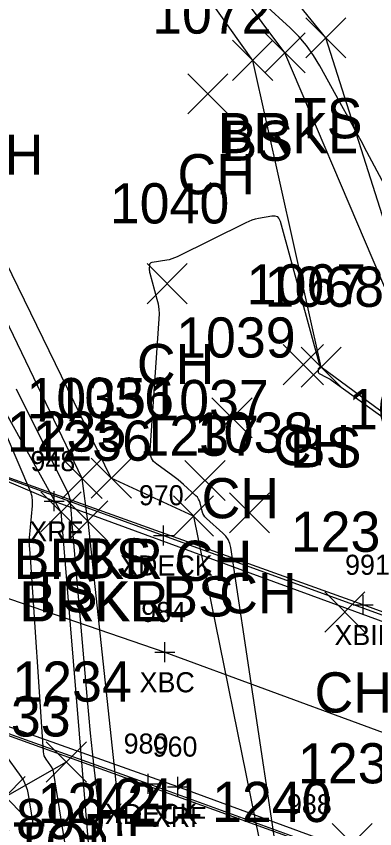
# Model space of a CAD drawing. Extents: x 1592612 to 1596497, y 111838 to 113741.
# Drawn here: x 1592864.37 to 1592882.21, y 113442.94 to 113483.39 of the extents above; entities that cross this region are included whole.
import ezdxf

# ---------------------------------------------------------------- set-up
doc = ezdxf.new("R2010")
doc.units = 0
for name, color, linetype in [('B_A', 7, 'Continuous'), ('B_I', 7, 'Continuous'), ('B_TIC', 7, 'Continuous'), ('BB', 7, 'Continuous'), ('BELB', 7, 'Continuous'), ('BR', 7, 'Continuous'), ('L_A', 7, 'Continuous'), ('L_I', 7, 'Continuous'), ('L_TIC', 7, 'Continuous'), ('LASF', 7, 'Continuous'), ('LAWE', 7, 'Continuous'), ('LELB', 7, 'Continuous'), ('LSOGCMI', 7, 'Continuous')]:
    doc.layers.add(name, color=color, linetype=linetype)

msp = doc.modelspace()

# ---------------------------------------------------------------- linework, layer by layer
at = {"layer": 'B_TIC'}
for p, q in [((1592866.258, 113459.246), (1592866.334, 113459.246)), ((1592871.698, 113457.547), (1592871.773, 113457.547)), ((1592881.637, 113454.085), (1592881.713, 113454.085)), ((1592871.771, 113451.736), (1592871.847, 113451.736)), ((1592870.939, 113445.184), (1592871.015, 113445.184)), ((1592872.405, 113445.033), (1592872.481, 113445.033))]:
    msp.add_line(p, q, dxfattribs=at)
for points in [[(1592866.255, 113458.746), (1592866.255, 113459.746)], [(1592865.755, 113459.246), (1592866.755, 113459.246)], [(1592871.694, 113457.047), (1592871.694, 113458.047)], [(1592871.194, 113457.547), (1592872.194, 113457.547)], [(1592881.634, 113453.585), (1592881.634, 113454.585)], [(1592881.134, 113454.085), (1592882.134, 113454.085)], [(1592871.768, 113451.236), (1592871.768, 113452.236)], [(1592871.268, 113451.736), (1592872.268, 113451.736)], [(1592870.936, 113444.684), (1592870.936, 113445.684)], [(1592872.402, 113444.533), (1592872.402, 113445.533)], [(1592870.436, 113445.184), (1592871.436, 113445.184)], [(1592871.902, 113445.033), (1592872.902, 113445.033)]]:
    msp.add_lwpolyline(points, dxfattribs=at)
at = {"layer": 'BB'}
for points in [[(1592909.632, 113443.83), (1592881.634, 113454.085), (1592854.88, 113463.68)], [(1592851.635, 113452.04), (1592879.022, 113442.165), (1592905.868, 113432.599)]]:
    msp.add_lwpolyline(points, dxfattribs=at)
at = {"layer": 'BELB'}
for points in [[(1592854.955, 113463.655), (1592871.694, 113457.547), (1592891.845, 113450.228), (1592909.596, 113443.74)], [(1592853.101, 113458.134), (1592871.768, 113451.736), (1592891.615, 113444.426), (1592907.694, 113438.543)], [(1592905.752, 113432.884), (1592904.3, 113433.154), (1592890.285, 113438.142), (1592870.936, 113445.184), (1592851.173, 113452.262)]]:
    msp.add_lwpolyline(points, dxfattribs=at)
at = {"layer": 'BR'}
for points in [[(1592852.564, 113465.029), (1592855.944, 113463.638), (1592866.255, 113459.246), (1592887.597, 113451.431), (1592909.085, 113443.965), (1592911.825, 113443.005)], [(1592908.092, 113431.674), (1592904.666, 113433.279), (1592893.882, 113437.15), (1592872.402, 113445.033), (1592848.761, 113453.419)]]:
    msp.add_lwpolyline(points, dxfattribs=at)
at = {"layer": 'L_TIC'}
for points in [[(1592878.778, 113481.314), (1592880.778, 113483.314)], [(1592880.778, 113481.314), (1592878.778, 113483.314)], [(1592876.744, 113480.574), (1592878.744, 113482.574)], [(1592878.744, 113480.574), (1592876.744, 113482.574)], [(1592875.137, 113480.194), (1592877.137, 113482.194)], [(1592877.137, 113480.194), (1592875.137, 113482.194)], [(1592872.901, 113478.528), (1592874.901, 113480.528)], [(1592874.901, 113478.528), (1592872.901, 113480.528)], [(1592870.88, 113469.078), (1592872.88, 113471.078)], [(1592872.88, 113469.078), (1592870.88, 113471.078)], [(1592877.654, 113465.043), (1592879.654, 113467.043)], [(1592879.654, 113465.043), (1592877.654, 113467.043)], [(1592878.544, 113464.926), (1592880.544, 113466.926)], [(1592880.544, 113464.926), (1592878.544, 113466.926)], [(1592874.103, 113462.399), (1592876.103, 113464.399)], [(1592876.103, 113462.399), (1592874.103, 113464.399)], [(1592866.645, 113459.38), (1592868.645, 113461.38)], [(1592868.645, 113459.38), (1592866.645, 113461.38)], [(1592868.098, 113459.398), (1592870.098, 113461.398)], [(1592870.098, 113459.398), (1592868.098, 113461.398)], [(1592872.762, 113459.283), (1592874.762, 113461.283)], [(1592874.762, 113459.283), (1592872.762, 113461.283)], [(1592865.59, 113457.717), (1592867.59, 113459.717)], [(1592867.59, 113457.717), (1592865.59, 113459.717)], [(1592874.976, 113457.667), (1592876.976, 113459.667)], [(1592876.976, 113457.667), (1592874.976, 113459.667)], [(1592866.922, 113457.263), (1592868.922, 113459.263)], [(1592868.922, 113457.263), (1592866.922, 113459.263)], [(1592866.922, 113457.263), (1592868.922, 113459.263)], [(1592868.922, 113457.263), (1592866.922, 113459.263)], [(1592872.192, 113457.509), (1592874.192, 113459.509)], [(1592874.192, 113457.509), (1592872.192, 113459.509)], [(1592879.724, 113452.73), (1592881.724, 113454.73)], [(1592881.724, 113452.73), (1592879.724, 113454.73)], [(1592865.863, 113445.27), (1592867.863, 113447.27)], [(1592867.863, 113445.27), (1592865.863, 113447.27)], [(1592865.863, 113445.27), (1592867.863, 113447.27)], [(1592867.863, 113445.27), (1592865.863, 113447.27)], [(1592862.817, 113443.537), (1592864.817, 113445.537)], [(1592864.817, 113443.537), (1592862.817, 113445.537)], [(1592862.817, 113443.537), (1592864.817, 113445.537)], [(1592864.817, 113443.537), (1592862.817, 113445.537)], [(1592880.09, 113441.203), (1592882.09, 113443.203)], [(1592882.09, 113441.203), (1592880.09, 113443.203)]]:
    msp.add_lwpolyline(points, dxfattribs=at)
at = {"layer": 'LASF'}
msp.add_lwpolyline([(1592859.003, 113448.358), (1592863.817, 113444.537), (1592866.863, 113446.27)], dxfattribs=at)
at = {"layer": 'LAWE'}
for points in [[(1592886.537, 113460.922), (1592877.744, 113481.574), (1592863.095, 113501.144), (1592852.902, 113518.209), (1592848.805, 113541.382), (1592835.879, 113571.623), (1592826.212, 113589.998), (1592821.08, 113603.103), (1592811.502, 113625.047), (1592801.909, 113656.496), (1592787.746, 113677.481), (1592769.551, 113701.793), (1592752.509, 113717.946)], [(1592867.645, 113460.38), (1592859.409, 113477.515), (1592844.793, 113495.549), (1592832.37, 113516.6), (1592826.928, 113530.545), (1592818.762, 113547.936), (1592807.597, 113581.108), (1592797.669, 113603.177), (1592787.513, 113626.88), (1592776.477, 113646.362), (1592766.38, 113665.342), (1592748.736, 113682.085), (1592730.356, 113695.945)], [(1592867.923, 113458.263), (1592867.645, 113460.38)], [(1592867.923, 113458.263), (1592869.843, 113440.453), (1592871.967, 113422.356), (1592872.93, 113405.001), (1592883.346, 113373.9), (1592893.179, 113344.656), (1592901.657, 113316.308), (1592912.684, 113311.087), (1592910.248, 113308.35), (1592916.07, 113291.076)]]:
    msp.add_lwpolyline(points, dxfattribs=at)
at = {"layer": 'LELB'}
for points in [[(1592886.583, 113460.952), (1592879.778, 113482.315), (1592863.966, 113501.755), (1592853.366, 113518.29), (1592851.192, 113542.037), (1592841.019, 113567.093), (1592831.516, 113591.894), (1592821.816, 113602.808), (1592813.329, 113624.79), (1592804.232, 113657.067), (1592789.644, 113678.369), (1592770.935, 113703.549), (1592752.623, 113718.428)], [(1592886.43, 113460.851), (1592879.543, 113465.926), (1592876.137, 113481.194), (1592862.304, 113500.643), (1592852.529, 113517.932), (1592848.162, 113540.894), (1592835.177, 113571.255), (1592825.196, 113589.927), (1592820.421, 113603.303), (1592810.027, 113625.391), (1592799.468, 113655.332), (1592786.607, 113676.744), (1592768.899, 113700.806), (1592752.213, 113717.027)], [(1592869.098, 113460.398), (1592860.441, 113478.115), (1592844.631, 113496.556), (1592834.165, 113516.964), (1592828.396, 113531.171), (1592823.559, 113549.918), (1592808.456, 113581.723), (1592799.527, 113603.061), (1592789.48, 113627.849), (1592777.21, 113647.427), (1592766.461, 113666.146), (1592749.422, 113683.288), (1592730.933, 113697.021)], [(1592866.59, 113458.717), (1592856.492, 113476.867)], [(1592873.192, 113458.509), (1592869.098, 113460.398)], [(1592866.59, 113458.717), (1592868.12, 113440.226), (1592870.678, 113422.668), (1592871.235, 113404.668), (1592883.079, 113373.124), (1592885.764, 113364.063), (1592892.434, 113344.134), (1592901.184, 113316.355)], [(1592873.192, 113458.509), (1592876.893, 113440.279), (1592874.766, 113422.722), (1592874.598, 113405.543), (1592883.851, 113374.09), (1592893.431, 113344.94), (1592902.258, 113316.43), (1592913.374, 113311.383), (1592911.324, 113309.219), (1592917.546, 113291.093), (1592922.314, 113282.948), (1592911.412, 113283.497), (1592902.691, 113283.749), (1592891.129, 113289.026)]]:
    msp.add_lwpolyline(points, dxfattribs=at)
at = {"layer": 'LSOGCMI'}
for points in [[(1592886.153, 113468.55), (1592881.816, 113476.647), (1592881.528, 113477.184), (1592881.238, 113477.72), (1592880.947, 113478.255), (1592880.654, 113478.789), (1592879.48, 113480.925), (1592879.167, 113481.443), (1592878.815, 113481.932), (1592878.425, 113482.389), (1592877.995, 113482.816), (1592875.379, 113485.215)], [(1592877.274, 113442.136), (1592875.051, 113456.937), (1592875.002, 113457.145), (1592874.92, 113457.336), (1592874.805, 113457.508), (1592874.657, 113457.663), (1592873.833, 113458.394), (1592873.76, 113458.469), (1592873.7, 113458.553), (1592873.654, 113458.645), (1592873.622, 113458.746), (1592873.52, 113459.164), (1592873.488, 113459.265), (1592873.443, 113459.357), (1592873.383, 113459.442), (1592873.311, 113459.518), (1592872.695, 113460.08), (1592872.564, 113460.196), (1592872.43, 113460.308), (1592872.293, 113460.416), (1592872.153, 113460.52), (1592871.359, 113461.09), (1592871.204, 113461.231), (1592871.098, 113461.394), (1592871.04, 113461.581), (1592871.031, 113461.79), (1592871.485, 113468.335), (1592871.491, 113468.577), (1592871.478, 113468.816), (1592871.444, 113469.053), (1592871.389, 113469.289), (1592871.032, 113470.589), (1592871.02, 113470.642), (1592871.011, 113470.695), (1592871.007, 113470.749), (1592871.007, 113470.803), (1592871.016, 113471.021), (1592871.024, 113471.07), (1592871.046, 113471.107), (1592871.08, 113471.133), (1592871.128, 113471.147), (1592871.862, 113471.262), (1592872.001, 113471.289), (1592872.136, 113471.327), (1592872.268, 113471.375), (1592872.397, 113471.433), (1592875.807, 113473.128), (1592875.958, 113473.196), (1592876.112, 113473.254), (1592876.27, 113473.3), (1592876.432, 113473.335), (1592877.086, 113473.452), (1592877.235, 113473.458), (1592877.354, 113473.416), (1592877.443, 113473.327), (1592877.501, 113473.19), (1592879.48, 113465.966), (1592879.483, 113465.95), (1592879.481, 113465.936), (1592879.475, 113465.922), (1592879.465, 113465.91), (1592879.417, 113465.864), (1592879.407, 113465.852), (1592879.399, 113465.838), (1592879.395, 113465.823), (1592879.394, 113465.807), (1592879.399, 113465.686), (1592879.402, 113465.662), (1592879.411, 113465.642), (1592879.426, 113465.625), (1592879.446, 113465.612), (1592879.799, 113465.432), (1592879.865, 113465.397), (1592879.929, 113465.36), (1592879.992, 113465.32), (1592880.053, 113465.278), (1592886.206, 113460.843)], [(1592864.359, 113464.844), (1592866.943, 113459.627), (1592866.987, 113459.526), (1592867.021, 113459.423), (1592867.044, 113459.316), (1592867.057, 113459.207), (1592867.089, 113458.763), (1592867.097, 113458.652), (1592867.105, 113458.541), (1592867.114, 113458.431), (1592867.124, 113458.32), (1592867.879, 113449.549), (1592867.962, 113448.625), (1592868.051, 113447.701), (1592868.148, 113446.779), (1592868.25, 113445.857), (1592868.675, 113442.17)], [(1592866.86, 113441.768), (1592866.244, 113445.696), (1592866.223, 113445.795), (1592866.19, 113445.891), (1592866.147, 113445.981), (1592866.093, 113446.067), (1592865.853, 113446.402), (1592865.799, 113446.489), (1592865.759, 113446.579), (1592865.733, 113446.675), (1592865.719, 113446.776), (1592865.071, 113456.467), (1592865.065, 113456.548), (1592865.06, 113456.628), (1592865.054, 113456.709), (1592865.047, 113456.789), (1592865.022, 113457.111), (1592865.017, 113457.191), (1592865.016, 113457.271), (1592865.019, 113457.352), (1592865.025, 113457.432), (1592865.179, 113459.023), (1592865.183, 113459.08), (1592865.184, 113459.137), (1592865.183, 113459.194), (1592865.178, 113459.251), (1592865.153, 113459.48), (1592865.145, 113459.536), (1592865.133, 113459.591), (1592865.116, 113459.646), (1592865.095, 113459.699), (1592863.13, 113464.241)], [(1592863.786, 113446.674), (1592864.589, 113445.551), (1592864.722, 113445.341), (1592864.828, 113445.121), (1592864.907, 113444.889), (1592864.959, 113444.647), (1592865.169, 113443.307), (1592865.175, 113443.234), (1592865.168, 113443.164), (1592865.149, 113443.095), (1592865.119, 113443.029), (1592864.972, 113442.769)]]:
    msp.add_lwpolyline(points, dxfattribs=at)

# ---------------------------------------------------------------- texts
at = {"layer": 'B_A'}
for s, p in [('XRF', (1592865.015, 113457.246)), ('XDECK', (1592869.537, 113455.547)), ('XBIB', (1592880.205, 113452.085)), ('XBC', (1592870.504, 113449.736)), ('XDECK', (1592868.778, 113443.184)), ('XRF', (1592871.162, 113443.033))]:
    msp.add_text(s, height=1, dxfattribs=at).set_placement(p)
at = {"layer": 'B_I'}
for s, p in [('948', (1592865.074, 113460.746)), ('970', (1592870.47, 113459.047)), ('991', (1592880.736, 113455.585)), ('984', (1592870.587, 113453.236)), ('980', (1592869.711, 113446.684)), ('960', (1592871.154, 113446.533)), ('988', (1592877.841, 113443.665))]:
    msp.add_text(s, height=1, dxfattribs=at).set_placement(p)
at = {"layer": 'L_A'}
for s, p in [('TS', (1592878.187, 113477.314)), ('BRKL', (1592874.389, 113476.574)), ('BS', (1592874.578, 113476.194)), ('CH', (1592861.848, 113475.498)), ('CH', (1592872.39, 113474.528)), ('CH', (1592870.368, 113465.078)), ('CH', (1592877.142, 113461.043)), ('BS', (1592877.985, 113460.926)), ('CH', (1592873.591, 113458.399)), ('BRKR', (1592864.236, 113455.38)), ('BS', (1592867.539, 113455.398)), ('CH', (1592872.25, 113455.283)), ('TS', (1592864.999, 113453.717)), ('BS', (1592871.633, 113453.509)), ('CH', (1592874.465, 113453.667)), ('BRKR', (1592864.513, 113453.263)), ('BRKL', (1592864.568, 113453.263)), ('CH', (1592879.212, 113448.73)), ('STONE', (1592862.407, 113441.27))]:
    msp.add_text(s, height=2, dxfattribs=at).set_placement(p)
at = {"layer": 'L_I'}
for s, p in [('1072', (1592871.13, 113482.528)), ('1040', (1592869.022, 113473.078)), ('1067', (1592875.835, 113469.043)), ('1068', (1592876.725, 113468.926)), ('1039', (1592872.324, 113466.399)), ('1035', (1592864.873, 113463.38)), ('1036', (1592866.271, 113463.398)), ('1037', (1592870.99, 113463.283)), ('1066', (1592880.887, 113462.833)), ('1235', (1592863.897, 113461.717)), ('1038', (1592873.205, 113461.667)), ('1236', (1592865.174, 113461.263)), ('1236', (1592865.174, 113461.263)), ('1237', (1592870.499, 113461.509)), ('1238', (1592878.031, 113456.73)), ('1234', (1592864.17, 113449.27)), ('1233', (1592861.124, 113447.537)), ('1239', (1592878.389, 113445.203)), ('1241', (1592867.717, 113443.453)), ('1242', (1592865.427, 113443.226)), ('1242', (1592865.427, 113443.226)), ('1240', (1592874.114, 113443.279)), ('899', (1592864.355, 113442.429))]:
    msp.add_text(s, height=2, dxfattribs=at).set_placement(p)

doc.saveas('drawing.dxf')
